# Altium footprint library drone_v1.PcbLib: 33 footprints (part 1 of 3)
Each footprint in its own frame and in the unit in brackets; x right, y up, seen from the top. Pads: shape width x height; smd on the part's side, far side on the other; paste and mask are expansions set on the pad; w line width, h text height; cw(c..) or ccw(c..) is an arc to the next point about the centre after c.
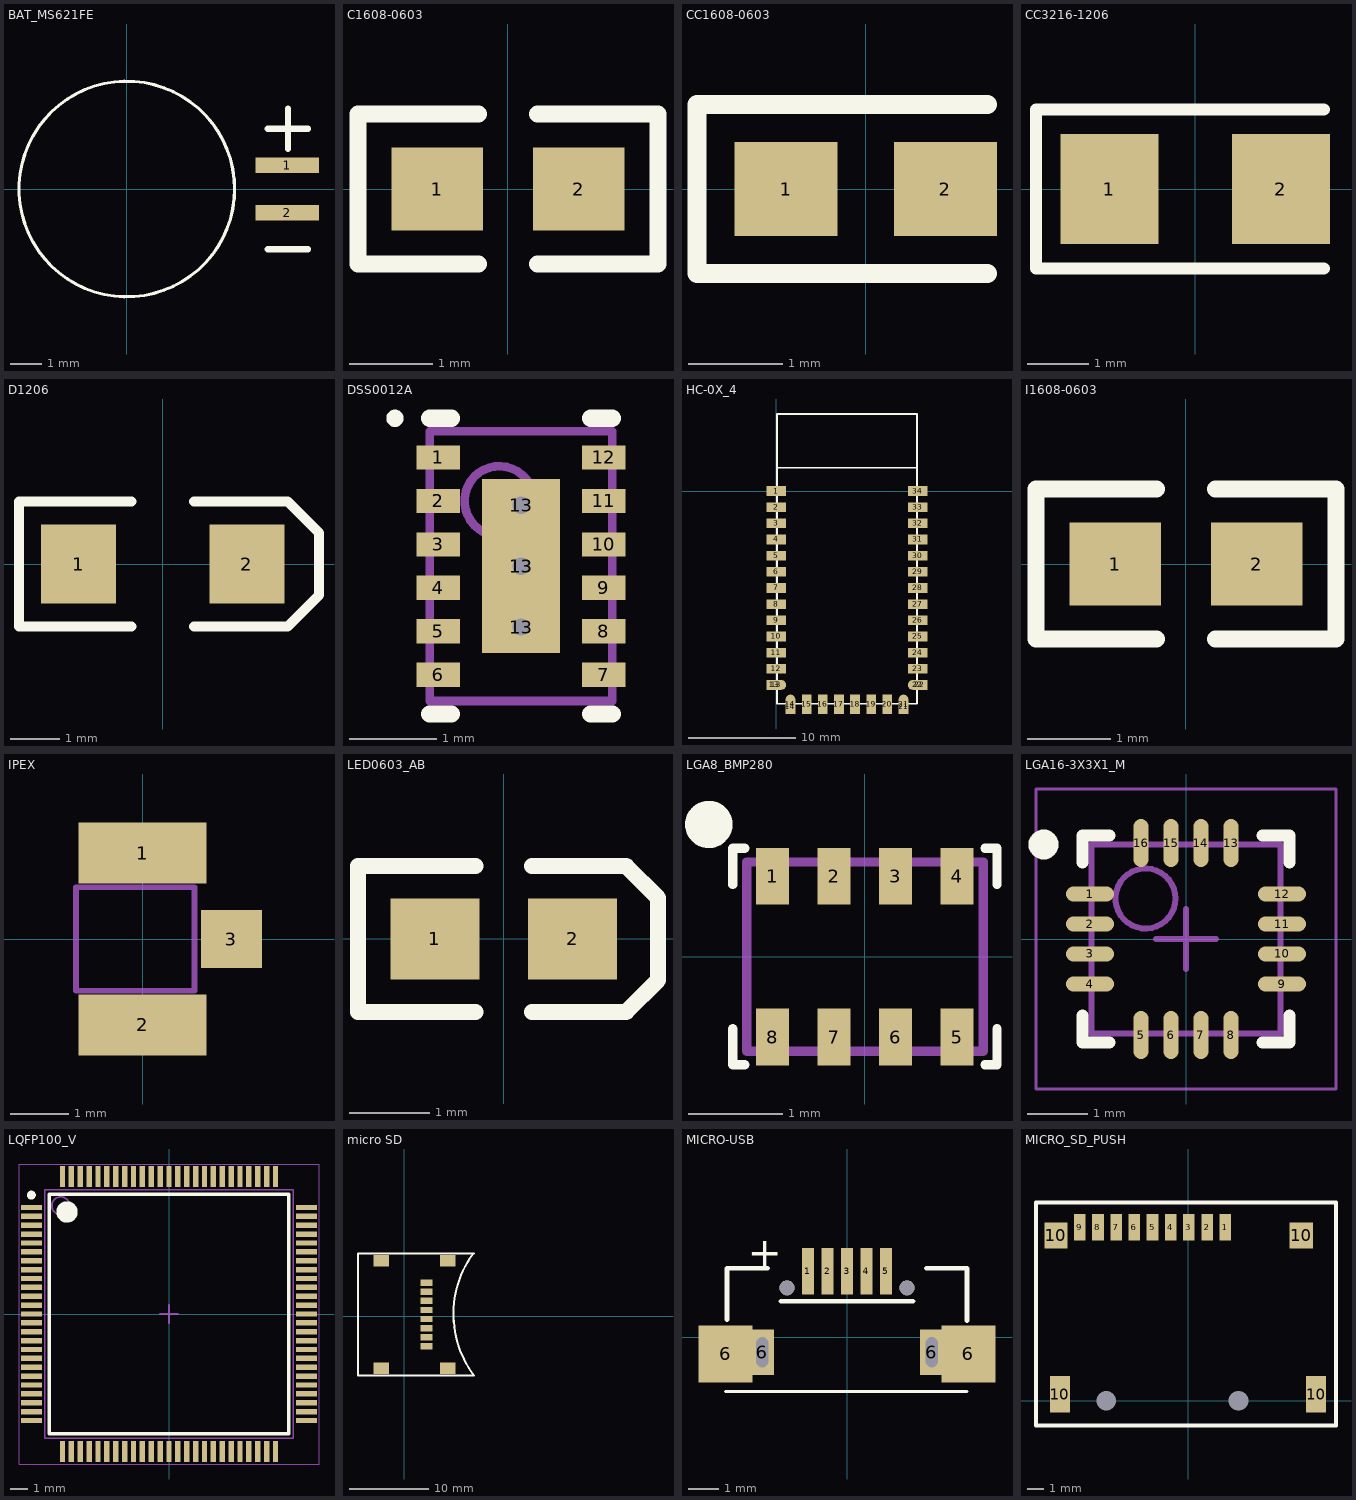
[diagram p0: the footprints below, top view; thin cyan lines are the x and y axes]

## BAT_MS621FE [mm]
pads (2):
  rect 2x0.5 smd paste+0 mask+0.05: 1(5.06,0.75) 2(5.06,-0.75)
Top Overlay:
  circle w0.1: c0,0 r3.4
  lines w0.2: 4.445,-1.905 5.715,-1.905 ; 4.445,1.905 5.715,1.905 ; 5.08,1.27 5.08,2.54

## C1608-0603 [mm]
pads (2):
  rect 1.1x1 smd: 1(-0.85,0) 2(0.85,0)
Top Overlay:
  lines w0.2: -0.35,-0.9 -1.8,-0.9 -1.8,0.9 -0.35,0.9 ; 0.35,-0.9 1.8,-0.9 1.8,0.9 0.35,0.9

## CC1608-0603 [mm]
pads (2):
  rect 1.1x1 smd: 1(-0.85,0) 2(0.85,0)
Top Overlay:
  lines w0.2: 1.3,-0.9 -1.8,-0.9 -1.8,0.9 1.3,0.9

## CC3216-1206 [mm]
pads (2):
  rect 1.6x1.8 smd: 1(-1.4,0) 2(1.4,0)
Top Overlay:
  lines w0.2: 2.1,-1.3 -2.6,-1.3 -2.6,1.3 2.1,1.3

## D1206 [mm]
pads (2):
  rect 1.52x1.6 smd: 1(-1.71,0) 2(1.71,0)
Top Overlay:
  lines w0.2: -0.635,-1.27 -2.921,-1.27 -2.921,1.27 -0.635,1.27 ; 0.635,-1.27 2.54,-1.27 3.175,-0.635 3.175,0.635 2.54,1.27 0.635,1.27

## DSS0012A [mm]
pads (16):
  rect 0.5x0.28 smd paste-0.14 mask+0.076: 1(47.31,52.05) 2(47.31,51.55) 3(47.31,51.05) 4(47.31,50.55) 5(47.31,50.05) 6(47.31,49.55) 7(49.21,49.55) 8(49.21,50.05) 9(49.21,50.55) 10(49.21,51.05) 11(49.21,51.55) 12(49.21,52.05)
  round 0.5 / inner round 1.524 / far side round 0.5 hole 0.2 mask+0.051: 13(48.26,50.8) 13(48.26,50.1) 13(48.26,51.5)
  rect 0.9x2 smd paste-0.45 mask+0.076: 13(48.26,50.8)
Top Overlay:
  circle w0.1: c46.81,52.5 r0.05
  lines w0.2: 47.21,49.1 47.46,49.1 ; 47.21,52.5 47.46,52.5 ; 49.06,49.1 49.31,49.1 ; 49.06,52.5 49.31,52.5
Top Paste:
  region: 47.06,51.175 47.06,50.925 47.56,50.925 47.56,51.175
  region: 47.885,52.5 47.885,51.9 48.135,51.9 48.135,52.5
  region: 47.91,51.6 47.91,50 48.61,50 48.61,51.6
  region: 48.635,51.9 48.635,52.5 48.385,52.5 48.385,51.9
  region: 48.635,49.1 48.635,49.7 48.385,49.7 48.385,49.1
  region: 47.885,49.7 47.885,49.1 48.135,49.1 48.135,49.7
  region: 47.06,51.675 47.06,51.425 47.56,51.425 47.56,51.675
  region: 47.06,52.175 47.06,51.925 47.56,51.925 47.56,52.175
  region: 47.06,50.675 47.06,50.425 47.56,50.425 47.56,50.675
  region: 47.06,50.175 47.06,49.925 47.56,49.925 47.56,50.175
  region: 47.06,49.675 47.06,49.425 47.56,49.425 47.56,49.675
  region: 48.96,49.675 48.96,49.425 49.46,49.425 49.46,49.675
  region: 48.96,50.175 48.96,49.925 49.46,49.925 49.46,50.175
  region: 48.96,50.675 48.96,50.425 49.46,50.425 49.46,50.675
  region: 48.96,51.175 48.96,50.925 49.46,50.925 49.46,51.175
  region: 48.96,51.675 48.96,51.425 49.46,51.425 49.46,51.675
  region: 48.96,52.175 48.96,51.925 49.46,51.925 49.46,52.175
Mechanical 1:
  circle w0.1: c48.01,51.55 r0.4
  lines w0.1: 47.21,49.25 47.21,52.35 49.31,52.35 49.31,49.25 47.21,49.25

## HC-0X_4 [mm]
pads (38):
  rect 1.8x0.9 smd: 1(0,0) 2(0,-1.5) 3(0,-3) 4(0,-4.5) 5(0,-6) 6(0,-7.5) 7(0,-9) 8(0,-10.5) 9(0,-12) 10(0,-13.5) 11(0,-15) 12(0,-16.5) 23(13.1,-16.5) 24(13.1,-15) 25(13.1,-13.5) 26(13.1,-12) 27(13.1,-10.5) 28(13.1,-9) 29(13.1,-7.5) 30(13.1,-6) 31(13.1,-4.5) 32(13.1,-3) 33(13.1,-1.5) 34(13.1,0)
  rect 1.35x0.9 smd: 13(-0.225,-18) 22(13.325,-18)
  oval 1.8x0.9 smd: 13(0,-18) 22(13.1,-18)
  rect 0.9x1.35 smd: 14(1.3,-20.025) 21(11.8,-20.025)
  oval 0.9x1.8 smd: 14(1.3,-19.8) 21(11.8,-19.8)
  rect 0.9x1.8 smd: 15(2.8,-19.8) 16(4.3,-19.8) 17(5.8,-19.8) 18(7.3,-19.8) 19(8.8,-19.8) 20(10.3,-19.8)
Top Overlay:
  lines w0.152: 0.05,2.15 13.05,2.15 ; 0.05,-19.75 0.05,7.15 13.05,7.15 13.05,-19.75 0.05,-19.75

## I1608-0603 [mm]
pads (2):
  rect 1.1x1 smd: 1(-0.85,0) 2(0.85,0)
Top Overlay:
  lines w0.2: -0.35,-0.9 -1.8,-0.9 -1.8,0.9 -0.35,0.9 ; 0.35,-0.9 1.8,-0.9 1.8,0.9 0.35,0.9

## IPEX [mm]
pads (3):
  rect 2.2x1.05 smd paste+0 mask+0.05: 1(0,1.475) 2(0,-1.475)
  rect 1.05x1 smd paste+0 mask+0.05: 3(1.525,0)
Mechanical 13:
  lines w0.1: -1.143,-0.889 -1.143,0.889 0.889,0.889 0.889,-0.889 -1.143,-0.889

## LED0603_AB [mm]
pads (2):
  rect 1.1x1 smd: 1(-0.85,0) 2(0.85,0)
Top Overlay:
  lines w0.2: -0.35,-0.9 -1.8,-0.9 -1.8,0.9 -0.35,0.9 ; 0.35,-0.9 1.513,-0.9 1.905,-0.508 1.905,0.508 1.513,0.9 0.35,0.9

## LGA8_BMP280 [mm]
pads (8):
  rect 0.35x0.6 smd paste+0 mask+0.03: 1(-0.975,0.85) 2(-0.325,0.85) 3(0.325,0.85) 4(0.975,0.85) 5(0.975,-0.85) 6(0.325,-0.85) 7(-0.325,-0.85) 8(-0.975,-0.85)
Top Overlay:
  circle w0.25: c-1.649,1.397 r0.125
  lines w0.1: -1.397,-0.762 -1.397,-1.143 -1.27,-1.143 ; -1.397,0.762 -1.397,1.143 -1.27,1.143 ; 1.27,-1.143 1.397,-1.143 1.397,-0.762 ; 1.27,1.143 1.397,1.143 1.397,0.762
Mechanical 13:
  lines w0.1: -1.25,-1 1.25,-1 1.25,1 -1.25,1 -1.25,-1

## LGA16-3X3X1_M [mm] "PQFN, 16-Leads, Body 3x3mm, Pitch 0.5mm, IPC Low Density"
height 1
pads (16):
  oval 0.8x0.25 smd: 1(-1.6,0.75) 2(-1.6,0.25) 3(-1.6,-0.25) 4(-1.6,-0.75) 9(1.6,-0.75) 10(1.6,-0.25) 11(1.6,0.25) 12(1.6,0.75)
  oval 0.25x0.8 smd: 5(-0.75,-1.6) 6(-0.25,-1.6) 7(0.25,-1.6) 8(0.75,-1.6) 13(0.75,1.6) 14(0.25,1.6) 15(-0.25,1.6) 16(-0.75,1.6)
Top Overlay:
  circle w0.25: c-2.375,1.575 r0.125
  lines w0.2: -1.725,-1.275 -1.725,-1.725 -1.275,-1.725 ; -1.725,1.275 -1.725,1.725 -1.275,1.725 ; 1.275,-1.725 1.725,-1.725 1.725,-1.275 ; 1.275,1.725 1.725,1.725 1.725,1.275
Mechanical 13:
  circle w0.1: c-0.675,0.675 r0.5
  lines w0.1: -1.575,-1.575 -1.575,1.575 1.575,1.575 1.575,-1.575 -1.575,-1.575
Mechanical 15:
  lines w0.05: -2.5,-2.5 -2.5,2.5 2.5,2.5 2.5,-2.5 -2.5,-2.5
  lines w0.1: -0.5,0 0.5,0 ; 0,-0.5 0,0.5
3D body: height 1, standoff 0, extent -1.575,-1.575 1.575,1.575

## LQFP100_V [mm] "Thin QFP, 100-Leads, Body 14x14mm, Pitch 0.5mm, ST Recommended"
height 1.6
pads (100):
  rect 1.2x0.3 smd: 1(-7.75,6) 2(-7.75,5.5) 3(-7.75,5) 4(-7.75,4.5) 5(-7.75,4) 6(-7.75,3.5) 7(-7.75,3) 8(-7.75,2.5) 9(-7.75,2) 10(-7.75,1.5) 11(-7.75,1) 12(-7.75,0.5) 13(-7.75,0) 14(-7.75,-0.5) 15(-7.75,-1) 16(-7.75,-1.5) 17(-7.75,-2) 18(-7.75,-2.5) 19(-7.75,-3) 20(-7.75,-3.5) 21(-7.75,-4) 22(-7.75,-4.5) 23(-7.75,-5) 24(-7.75,-5.5) 25(-7.75,-6) 51(7.75,-6) 52(7.75,-5.5) 53(7.75,-5) 54(7.75,-4.5) 55(7.75,-4) 56(7.75,-3.5) 57(7.75,-3) 58(7.75,-2.5) 59(7.75,-2) 60(7.75,-1.5) 61(7.75,-1) 62(7.75,-0.5) 63(7.75,0) 64(7.75,0.5) 65(7.75,1) 66(7.75,1.5) 67(7.75,2) 68(7.75,2.5) 69(7.75,3) 70(7.75,3.5) 71(7.75,4) 72(7.75,4.5) 73(7.75,5) 74(7.75,5.5) 75(7.75,6)
  rect 0.3x1.2 smd: 26(-6,-7.75) 27(-5.5,-7.75) 28(-5,-7.75) 29(-4.5,-7.75) 30(-4,-7.75) 31(-3.5,-7.75) 32(-3,-7.75) 33(-2.5,-7.75) 34(-2,-7.75) 35(-1.5,-7.75) 36(-1,-7.75) 37(-0.5,-7.75) 38(0,-7.75) 39(0.5,-7.75) 40(1,-7.75) 41(1.5,-7.75) 42(2,-7.75) 43(2.5,-7.75) 44(3,-7.75) 45(3.5,-7.75) 46(4,-7.75) 47(4.5,-7.75) 48(5,-7.75) 49(5.5,-7.75) 50(6,-7.75) 76(6,7.75) 77(5.5,7.75) 78(5,7.75) 79(4.5,7.75) 80(4,7.75) 81(3.5,7.75) 82(3,7.75) 83(2.5,7.75) 84(2,7.75) 85(1.5,7.75) 86(1,7.75) 87(0.5,7.75) 88(0,7.75) 89(-0.5,7.75) 90(-1,7.75) 91(-1.5,7.75) 92(-2,7.75) 93(-2.5,7.75) 94(-3,7.75) 95(-3.5,7.75) 96(-4,7.75) 97(-4.5,7.75) 98(-5,7.75) 99(-5.5,7.75) 100(-6,7.75)
Top Overlay:
  circle w0.25: c-7.75,6.7 r0.125
  circle w0.6: c-5.75,5.75 r0.3
  lines w0.2: -6.75,-6.75 -6.75,6.75 6.75,6.75 6.75,-6.75 -6.75,-6.75
Mechanical 13:
  circle w0.1: c-6.1,6.1 r0.5
  lines w0.1: -7,-7 -7,7 7,7 7,-7 -7,-7
Mechanical 15:
  lines w0.05: -8.45,-8.45 -8.45,8.45 8.45,8.45 8.45,-8.45 -8.45,-8.45
  lines w0.1: -0.5,0 0.5,0 ; 0,-0.5 0,0.5
3D body: height 1.6, standoff 0.05, extent -7,-7 7,7

## micro SD [mm]
pads (12):
  rect 1.5x0.8 smd: 1(2.794,4.191) 2(2.794,3.048) 3(2.794,1.905) 4(2.794,0.762) 5(2.794,-0.381) 6(2.794,-1.524) 7(2.794,-2.667) 8(2.794,-3.81)
  rect 2x1.45 smd: ""(-2.921,-6.604) ""(-2.921,6.985) ""(5.461,-6.604) ""(5.461,6.985)
Top Overlay:
  lines w0.254: 8.614,7.798 ccw(c19.05,0.254) 8.763,-7.493 -5.842,-7.493 -5.842,7.874 8.763,7.874

## MICRO-USB [mm]
pads (11):
  rect 0.4x1.55 smd: 1(-1.3,2.2) 2(-0.65,2.2) 3(0,2.2) 4(0.65,2.2) 5(1.3,2.2)
  rect 1.8x1.9 smd: 6(-4.05,-0.55) 6(4.05,-0.55)
  rect 0.8x1.5 hole 0.4 slot 1 at 90 deg: 6(-2.825,-0.5) 6(2.825,-0.5)
  round 0.5 hole 0.5 unplated: ""(-2,1.65) ""(2,1.65)
Top Overlay:
  lines w0.1: -4.05,-1.8 4,-1.8
  lines w0.152: -4,0.584 -4,2.3 -2.65,2.3 ; -2.2,1.2 2.2,1.2 ; 2.65,2.3 4,2.3 4,0.55
  text "+" at -3.3,2.35 h1

## MICRO_SD_PUSH [mm]
pads (15):
  rect 0.7x1.6 smd: 1(2.25,10.5) 2(1.15,10.5) 3(0.05,10.5) 4(-1.05,10.5) 5(-2.15,10.5) 6(-3.25,10.5) 7(-4.35,10.5) 8(-5.45,10.5) 9(-6.55,10.5)
  rect 1.4x1.6 smd: 10(-8,10) 10(6.85,10)
  rect 1.2x2.2 smd: 10(-7.75,0.4) 10(7.75,0.4)
  round 1 hole 1.2: ""(-4.95,0) ""(3.05,0)
Top Overlay:
  lines w0.254: -9.2,-1.5 -9.2,12 8.95,12 8.95,-1.5 -9.2,-1.5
